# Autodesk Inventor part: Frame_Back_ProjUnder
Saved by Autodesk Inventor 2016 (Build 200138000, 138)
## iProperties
Created: 2015-11
Part Number: Frame_Back_ProjUnder
Material: Generic
Document SubType Name: Modeling
Designer: John
Density: 1 g/cm^3
Appearance: Default
Author: John
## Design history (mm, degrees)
feature "Base1"
body "Solid1"
